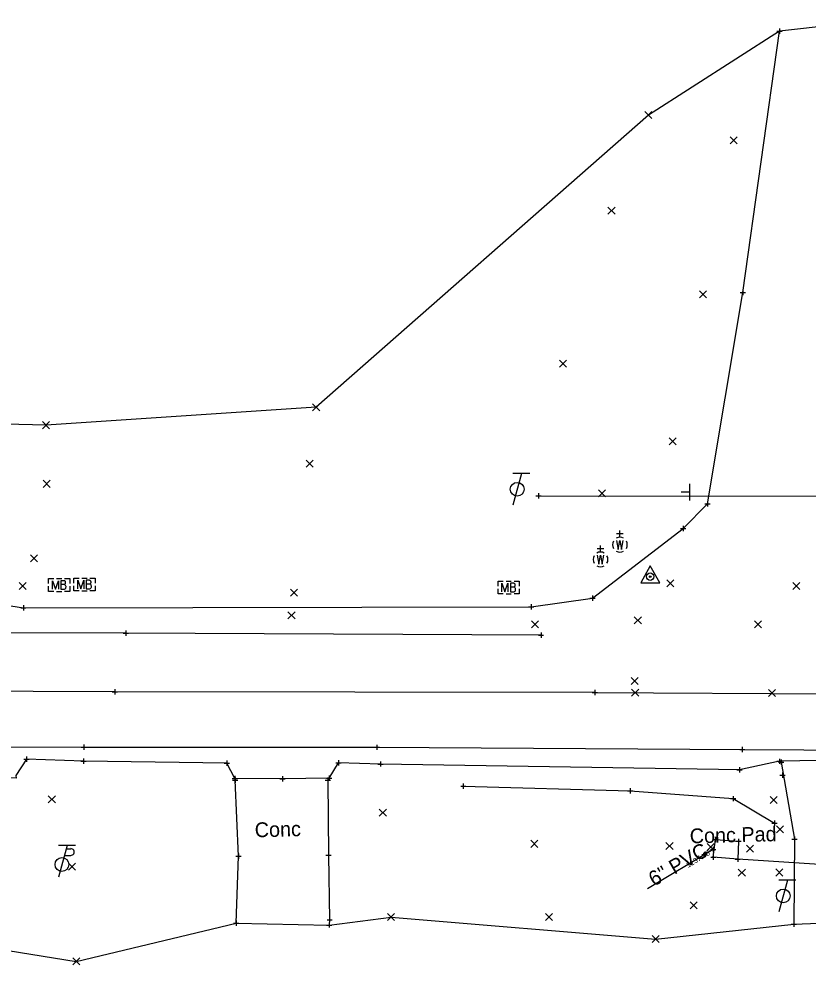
# Model space of a CAD drawing. Extents: x 146022 to 147632, y 437624 to 440659.
# Drawn here: x 146651.9 to 146801.3, y 438576.8 to 438756.1 of the extents above; entities that cross this region are included whole.
import ezdxf

# ---------------------------------------------------------------- set-up
doc = ezdxf.new("R2010")
doc.units = 0
for name, color, linetype in [('_CIVIL_CONSTRUCTION', 7, 'Continuous'), ('DR_P_Ditch', 7, 'Continuous'), ('DR_X_Storm_Sewer', 7, 'Continuous'), ('DR_X_Text', 7, 'Continuous'), ('DT_X_Break_Line', 7, 'Continuous'), ('DT_X_Contour_Major', 7, 'Continuous'), ('DT_X_Spot_Elev', 7, 'Continuous'), ('GE_P_Alignment_100_Distances', 7, 'Continuous'), ('PF_X_Ground_Line', 7, 'Continuous'), ('PV_P_Curb', 7, 'Continuous'), ('PV_P_Joint', 7, 'Continuous'), ('RD_P_Anchor_Assembly', 7, 'Continuous'), ('RD_P_GR_Lt_Replaced', 7, 'Continuous'), ('RD_P_GR_Rt', 7, 'Continuous'), ('SC_Scratch1', 7, 'Continuous'), ('SC_Scratch3', 7, 'Continuous'), ('SV_X_Terrain_Boundary', 7, 'Continuous'), ('UT_X_Overhead_Cable_TV', 7, 'Continuous'), ('UT_X_Overhead_Electric', 7, 'Continuous')]:
    doc.layers.add(name, color=color, linetype=linetype)

msp = doc.modelspace()

# ---------------------------------------------------------------- linework, layer by layer
at = {"layer": '_CIVIL_CONSTRUCTION'}
for p, q in [((146770.39, 438737.25), (146771.72, 438738.58)), ((146770.39, 438738.58), (146771.72, 438737.25)), ((146786.49, 438732.48), (146787.82, 438733.81)), ((146786.49, 438733.81), (146787.82, 438732.48)), ((146763.39, 438719.14), (146764.72, 438720.47)), ((146763.39, 438720.47), (146764.72, 438719.14)), ((146780.69, 438703.32), (146782.02, 438704.65)), ((146780.69, 438704.65), (146782.02, 438703.32)), ((146754.18, 438690.19), (146755.51, 438691.52)), ((146754.18, 438691.52), (146755.51, 438690.19)), ((146707.47, 438681.91), (146708.81, 438683.24)), ((146707.47, 438683.24), (146708.81, 438681.91)), ((146656.34, 438678.53), (146657.67, 438679.87)), ((146656.34, 438679.87), (146657.67, 438678.53)), ((146774.98, 438675.45), (146776.31, 438676.79)), ((146774.98, 438676.79), (146776.31, 438675.45)), ((146706.24, 438671.25), (146707.58, 438672.58)), ((146706.24, 438672.58), (146707.58, 438671.25)), ((146656.48, 438667.42), (146657.82, 438668.76)), ((146656.48, 438668.76), (146657.82, 438667.42)), ((146761.58, 438665.63), (146762.91, 438666.97)), ((146761.58, 438666.97), (146762.91, 438665.63)), ((146654.06, 438653.3), (146655.4, 438654.64)), ((146654.06, 438654.64), (146655.4, 438653.3)), ((146651.92, 438648.08), (146653.25, 438649.41)), ((146651.92, 438649.41), (146653.25, 438648.08)), ((146774.53, 438648.59), (146775.86, 438649.92)), ((146774.53, 438649.92), (146775.86, 438648.59)), ((146798.37, 438648.08), (146799.7, 438649.41)), ((146798.37, 438649.41), (146799.7, 438648.08)), ((146703.31, 438646.79), (146704.64, 438648.12)), ((146703.31, 438648.12), (146704.64, 438646.79)), ((146702.8, 438642.52), (146704.14, 438643.86)), ((146702.8, 438643.86), (146704.14, 438642.52)), ((146748.91, 438640.83), (146750.24, 438642.16)), ((146748.91, 438642.16), (146750.24, 438640.83)), ((146768.37, 438641.59), (146769.71, 438642.93)), ((146768.37, 438642.93), (146769.71, 438641.59)), ((146791.12, 438640.81), (146792.45, 438642.15)), ((146791.12, 438642.15), (146792.45, 438640.81)), ((146767.78, 438630.09), (146769.11, 438631.42)), ((146767.78, 438631.42), (146769.11, 438630.09)), ((146767.87, 438627.86), (146769.2, 438629.19)), ((146767.87, 438629.19), (146769.2, 438627.86)), ((146793.8, 438627.8), (146795.13, 438629.13)), ((146793.8, 438629.13), (146795.13, 438627.8)), ((146657.44, 438607.67), (146658.77, 438609)), ((146657.44, 438609), (146658.77, 438607.67)), ((146794.08, 438607.55), (146795.41, 438608.88)), ((146794.08, 438608.88), (146795.41, 438607.55)), ((146720.09, 438605.14), (146721.43, 438606.47)), ((146720.09, 438606.47), (146721.43, 438605.14)), ((146795.26, 438602.01), (146796.6, 438603.35)), ((146795.26, 438603.35), (146796.6, 438602.01)), ((146748.8, 438599.25), (146750.13, 438600.59)), ((146748.8, 438600.59), (146750.13, 438599.25)), ((146774.36, 438598.82), (146775.7, 438600.16)), ((146774.36, 438600.16), (146775.7, 438598.82)), ((146782.15, 438598.63), (146783.48, 438599.96)), ((146782.15, 438599.96), (146783.48, 438598.63)), ((146789.62, 438598.32), (146790.95, 438599.65)), ((146789.62, 438599.65), (146790.95, 438598.32)), ((146661.24, 438594.91), (146662.58, 438596.24)), ((146661.24, 438596.24), (146662.58, 438594.91)), ((146788.06, 438593.79), (146789.39, 438595.12)), ((146788.06, 438595.12), (146789.39, 438593.79)), ((146795.16, 438593.81), (146796.49, 438595.15)), ((146795.16, 438595.15), (146796.49, 438593.81)), ((146778.94, 438587.58), (146780.27, 438588.92)), ((146778.94, 438588.92), (146780.27, 438587.58)), ((146721.66, 438585.37), (146722.99, 438586.71)), ((146721.66, 438586.71), (146722.99, 438585.37)), ((146751.53, 438585.38), (146752.86, 438586.71)), ((146751.53, 438586.71), (146752.86, 438585.38)), ((146771.73, 438581.2), (146773.06, 438582.54)), ((146771.73, 438582.54), (146773.06, 438581.2)), ((146662.05, 438576.98), (146663.38, 438578.32)), ((146662.05, 438578.32), (146663.38, 438576.98))]:
    msp.add_line(p, q, dxfattribs=at)
at = {"layer": 'DR_P_Ditch'}
msp.add_lwpolyline([(146787.94, 438597.01), (146783.33, 438597.39), (146783.74, 438600.71), (146788.12, 438600.39)], close=True, dxfattribs=at)
at = {"layer": 'DR_X_Storm_Sewer'}
for p, q in [((146783.32, 438598.84), (146770.88, 438591.4)), ((146872.73, 438591.35), (146787.94, 438597.01))]:
    msp.add_line(p, q, dxfattribs=at)
at = {"layer": 'DT_X_Break_Line'}
for p, q in [((146778.85, 438668.11), (146778.85, 438664.91)), ((146778.85, 438666.51), (146777.25, 438666.51))]:
    msp.add_line(p, q, dxfattribs=at)
at = {"layer": 'DT_X_Contour_Major'}
for p, q in [((146660.99, 438599.6), (146659.38, 438593.6)), ((146662.59, 438599.6), (146659.39, 438599.6)), ((146660.83, 438599), (146661.68, 438599)), ((146660.49, 438597.73), (146661.68, 438597.73))]:
    msp.add_line(p, q, dxfattribs=at)
msp.add_circle((146660.02, 438596), 1.3, dxfattribs=at)
msp.add_arc((146661.69, 438598.37), 0.638, 268.8767, 91.1233, dxfattribs=at)
at = {"layer": 'DT_X_Spot_Elev'}
for p, q in [((146658.99, 438650.17), (146659.99, 438650.17)), ((146663.79, 438650.24), (146664.79, 438650.24)), ((146659.5, 438648.95), (146659.5, 438648.95)), ((146664.3, 438649.02), (146664.3, 438649.02)), ((146744.09, 438649.67), (146745.09, 438649.67)), ((146744.6, 438648.45), (146744.6, 438648.45)), ((146658.99, 438647.73), (146659.99, 438647.73)), ((146663.79, 438647.8), (146664.79, 438647.8)), ((146744.09, 438647.23), (146745.09, 438647.23))]:
    msp.add_line(p, q, dxfattribs=at)
for points in [[(146657.5, 438649.2), (146657.5, 438650.17), (146658.47, 438650.17)], [(146660.5, 438650.17), (146661.5, 438650.17), (146661.5, 438649.2)], [(146662.3, 438649.27), (146662.3, 438650.24), (146663.27, 438650.24)], [(146665.31, 438650.24), (146666.3, 438650.24), (146666.3, 438649.27)], [(146658.47, 438647.73), (146657.5, 438647.73), (146657.5, 438648.7)], [(146658.2, 438648.15), (146658.2, 438649.75), (146658.78, 438648.15), (146659.34, 438649.75), (146659.34, 438648.15)], [(146660.52, 438649.02), (146660.58, 438649.08), (146660.62, 438649.12), (146660.65, 438649.16), (146660.66, 438649.18), (146660.68, 438649.23), (146660.7, 438649.27), (146660.72, 438649.36), (146660.72, 438649.4), (146660.72, 438649.45), (146660.71, 438649.52), (146660.68, 438649.59), (146660.65, 438649.64), (146660.58, 438649.69), (146660.53, 438649.71), (146660.51, 438649.73), (146660.44, 438649.75), (146659.83, 438649.75), (146659.83, 438648.15), (146660.52, 438648.15), (146660.61, 438648.2), (146660.68, 438648.26), (146660.75, 438648.36), (146660.78, 438648.48), (146660.8, 438648.59), (146660.8, 438648.67), (146660.77, 438648.74), (146660.72, 438648.86), (146660.66, 438648.93), (146660.52, 438649.02), (146659.83, 438649.02)], [(146661.5, 438648.7), (146661.5, 438647.73), (146660.5, 438647.73)], [(146663.27, 438647.8), (146662.3, 438647.8), (146662.3, 438648.77)], [(146663, 438648.22), (146663, 438649.82), (146663.58, 438648.22), (146664.14, 438649.82), (146664.14, 438648.22)], [(146665.32, 438649.09), (146665.38, 438649.15), (146665.42, 438649.19), (146665.45, 438649.23), (146665.46, 438649.25), (146665.49, 438649.3), (146665.5, 438649.34), (146665.52, 438649.43), (146665.52, 438649.47), (146665.52, 438649.52), (146665.51, 438649.59), (146665.49, 438649.65), (146665.45, 438649.7), (146665.38, 438649.76), (146665.33, 438649.78), (146665.31, 438649.79), (146665.25, 438649.82), (146664.63, 438649.82), (146664.63, 438648.22), (146665.32, 438648.22), (146665.41, 438648.27), (146665.49, 438648.33), (146665.55, 438648.43), (146665.59, 438648.55), (146665.6, 438648.66), (146665.6, 438648.73), (146665.57, 438648.81), (146665.52, 438648.92), (146665.46, 438649), (146665.32, 438649.09), (146664.63, 438649.09)], [(146666.3, 438648.77), (146666.3, 438647.8), (146665.31, 438647.8)], [(146742.6, 438648.7), (146742.6, 438649.67), (146743.57, 438649.67)], [(146743.3, 438647.65), (146743.3, 438649.25), (146743.88, 438647.65), (146744.44, 438649.25), (146744.44, 438647.65)], [(146745.62, 438648.52), (146745.69, 438648.59), (146745.72, 438648.62), (146745.75, 438648.66), (146745.76, 438648.69), (146745.79, 438648.74), (146745.8, 438648.77), (146745.82, 438648.86), (146745.82, 438648.9), (146745.82, 438648.95), (146745.81, 438649.03), (146745.79, 438649.09), (146745.75, 438649.14), (146745.69, 438649.19), (146745.64, 438649.22), (146745.61, 438649.23), (146745.55, 438649.25), (146744.93, 438649.25), (146744.93, 438647.65), (146745.62, 438647.65), (146745.71, 438647.7), (146745.79, 438647.77), (146745.85, 438647.87), (146745.89, 438647.98), (146745.9, 438648.09), (146745.9, 438648.17), (146745.87, 438648.25), (146745.82, 438648.36), (146745.76, 438648.43), (146745.62, 438648.52), (146744.93, 438648.52)], [(146745.61, 438649.67), (146746.6, 438649.67), (146746.6, 438648.7)], [(146743.57, 438647.23), (146742.6, 438647.23), (146742.6, 438648.2)], [(146746.6, 438648.2), (146746.6, 438647.23), (146745.61, 438647.23)]]:
    msp.add_lwpolyline(points, dxfattribs=at)
at = {"layer": 'GE_P_Alignment_100_Distances'}
msp.add_lwpolyline([(146750.22, 438665.83), (146889.21, 438665.72), (146992.98, 438665.29), (147118.65, 438665.14)], dxfattribs=at)
at = {"layer": 'PF_X_Ground_Line'}
msp.add_lwpolyline([(146736, 438610.82), (146767.59, 438609.97), (146787.08, 438608.47), (146794.92, 438603.81)], dxfattribs=at)
at = {"layer": 'PV_P_Curb'}
msp.add_line((146760.89, 438628.57), (146831.42, 438628.2), dxfattribs=at)
msp.add_lwpolyline([(146760.89, 438628.57), (146670.03, 438628.72), (146608.22, 438628.98), (146536.84, 438628.93)], dxfattribs=at)
at = {"layer": 'PV_P_Joint'}
msp.add_lwpolyline([(146769.58, 438649.36), (146773.18, 438649.36), (146771.38, 438652.58)], close=True, dxfattribs=at)
for radius in [0.7, 0.16]:
    msp.add_circle((146771.38, 438650.51), radius, dxfattribs=at)
at = {"layer": 'RD_P_Anchor_Assembly'}
for p, q in [((146795.88, 438754.29), (146795.88, 438753.29)), ((146795.38, 438753.79), (146796.38, 438753.79)), ((146795.88, 438753.79), (146795.88, 438753.79)), ((146788.41, 438704.34), (146789.41, 438704.34)), ((146788.91, 438704.84), (146788.91, 438703.84)), ((146788.91, 438704.34), (146788.91, 438704.34)), ((146750.22, 438666.33), (146750.22, 438665.33)), ((146749.72, 438665.83), (146750.72, 438665.83)), ((146750.22, 438665.83), (146750.22, 438665.83)), ((146782.21, 438664.81), (146782.21, 438663.81)), ((146781.71, 438664.31), (146782.71, 438664.31)), ((146782.21, 438664.31), (146782.21, 438664.31)), ((146777.12, 438659.64), (146778.12, 438659.64)), ((146777.62, 438660.14), (146777.62, 438659.14)), ((146777.62, 438659.64), (146777.62, 438659.64)), ((146760.43, 438646.95), (146760.43, 438645.95)), ((146652.71, 438645.13), (146652.71, 438644.13)), ((146748.33, 438644.78), (146749.33, 438644.78)), ((146748.83, 438645.28), (146748.83, 438644.28)), ((146748.83, 438644.78), (146748.83, 438644.78)), ((146759.93, 438646.45), (146760.93, 438646.45)), ((146760.43, 438646.45), (146760.43, 438646.45)), ((146652.21, 438644.63), (146653.21, 438644.63)), ((146652.71, 438644.63), (146652.71, 438644.63)), ((146671.62, 438639.82), (146672.62, 438639.82)), ((146672.12, 438640.32), (146672.12, 438639.32)), ((146672.12, 438639.82), (146672.12, 438639.82)), ((146750.21, 438639.45), (146751.21, 438639.45)), ((146750.71, 438639.95), (146750.71, 438638.95)), ((146750.71, 438639.45), (146750.71, 438639.45)), ((146669.53, 438628.72), (146670.53, 438628.72)), ((146670.03, 438629.22), (146670.03, 438628.22)), ((146670.03, 438628.72), (146670.03, 438628.72)), ((146760.89, 438629.07), (146760.89, 438628.07)), ((146760.39, 438628.57), (146761.39, 438628.57)), ((146760.89, 438628.57), (146760.89, 438628.57)), ((146663.65, 438618.22), (146664.65, 438618.22)), ((146664.15, 438618.72), (146664.15, 438617.72)), ((146664.15, 438618.22), (146664.15, 438618.22)), ((146719.14, 438618.19), (146720.14, 438618.19)), ((146719.64, 438618.69), (146719.64, 438617.69)), ((146719.64, 438618.19), (146719.64, 438618.19)), ((146788.82, 438618.3), (146788.82, 438617.3)), ((146653.33, 438616.44), (146653.33, 438615.44)), ((146664.1, 438616.08), (146664.1, 438615.08)), ((146788.32, 438617.8), (146789.32, 438617.8)), ((146788.82, 438617.8), (146788.82, 438617.8)), ((146795.87, 438616.04), (146795.87, 438615.04)), ((146652.83, 438615.94), (146653.83, 438615.94)), ((146653.33, 438615.94), (146653.33, 438615.94)), ((146663.6, 438615.58), (146664.6, 438615.58)), ((146664.1, 438615.58), (146664.1, 438615.58)), ((146690.76, 438615.19), (146691.76, 438615.19)), ((146691.26, 438615.69), (146691.26, 438614.69)), ((146691.26, 438615.19), (146691.26, 438615.19)), ((146711.85, 438615.26), (146712.85, 438615.26)), ((146712.35, 438615.76), (146712.35, 438614.76)), ((146712.35, 438615.26), (146712.35, 438615.26)), ((146719.81, 438615.03), (146720.81, 438615.03)), ((146720.31, 438615.53), (146720.31, 438614.53)), ((146720.31, 438615.03), (146720.31, 438615.03)), ((146788.31, 438614.43), (146788.31, 438613.43)), ((146795.37, 438615.54), (146796.37, 438615.54)), ((146795.68, 438615.39), (146796.68, 438615.39)), ((146795.87, 438615.54), (146795.87, 438615.54)), ((146796.18, 438615.89), (146796.18, 438614.89)), ((146796.18, 438615.39), (146796.18, 438615.39)), ((146692.77, 438612.79), (146692.77, 438611.79)), ((146692.79, 438612.49), (146692.79, 438611.49)), ((146701.78, 438612.72), (146701.78, 438611.72)), ((146710.35, 438612.46), (146710.35, 438611.46)), ((146710.58, 438612.83), (146710.58, 438611.83)), ((146787.81, 438613.93), (146788.81, 438613.93)), ((146788.31, 438613.93), (146788.31, 438613.93)), ((146795.93, 438612.92), (146796.93, 438612.92)), ((146796.43, 438613.42), (146796.43, 438612.42)), ((146796.43, 438612.92), (146796.43, 438612.92)), ((146692.27, 438612.29), (146693.27, 438612.29)), ((146692.29, 438611.99), (146693.29, 438611.99)), ((146692.77, 438612.29), (146692.77, 438612.29)), ((146692.79, 438611.99), (146692.79, 438611.99)), ((146701.28, 438612.22), (146702.28, 438612.22)), ((146701.78, 438612.22), (146701.78, 438612.22)), ((146709.85, 438611.96), (146710.85, 438611.96)), ((146710.08, 438612.33), (146711.08, 438612.33)), ((146710.35, 438611.96), (146710.35, 438611.96)), ((146710.58, 438612.33), (146710.58, 438612.33)), ((146735.5, 438610.82), (146736.5, 438610.82)), ((146736, 438611.32), (146736, 438610.32)), ((146736, 438610.82), (146736, 438610.82)), ((146767.09, 438609.97), (146768.09, 438609.97)), ((146767.59, 438610.47), (146767.59, 438609.47)), ((146767.59, 438609.97), (146767.59, 438609.97)), ((146787.08, 438608.97), (146787.08, 438607.97)), ((146786.58, 438608.47), (146787.58, 438608.47)), ((146787.08, 438608.47), (146787.08, 438608.47)), ((146794.42, 438603.81), (146795.42, 438603.81)), ((146794.92, 438604.31), (146794.92, 438603.31)), ((146794.92, 438603.81), (146794.92, 438603.81)), ((146783.24, 438600.71), (146784.24, 438600.71)), ((146783.74, 438601.21), (146783.74, 438600.21)), ((146783.74, 438600.71), (146783.74, 438600.71)), ((146787.62, 438600.39), (146788.62, 438600.39)), ((146788.12, 438600.89), (146788.12, 438599.89)), ((146788.12, 438600.39), (146788.12, 438600.39)), ((146798.19, 438600.83), (146799.19, 438600.83)), ((146798.69, 438601.33), (146798.69, 438600.33)), ((146798.69, 438600.83), (146798.69, 438600.83)), ((146710.5, 438598.3), (146710.5, 438597.3)), ((146692.93, 438597.59), (146693.93, 438597.59)), ((146693.43, 438598.09), (146693.43, 438597.09)), ((146693.43, 438597.59), (146693.43, 438597.59)), ((146710, 438597.8), (146711, 438597.8)), ((146710.5, 438597.8), (146710.5, 438597.8)), ((146782.83, 438597.39), (146783.83, 438597.39)), ((146783.33, 438597.89), (146783.33, 438596.89)), ((146783.33, 438597.39), (146783.33, 438597.39)), ((146787.44, 438597.01), (146788.44, 438597.01)), ((146787.94, 438597.51), (146787.94, 438596.51)), ((146787.94, 438597.01), (146787.94, 438597.01)), ((146710.2, 438585.55), (146711.2, 438585.55)), ((146710.7, 438586.05), (146710.7, 438585.05)), ((146710.7, 438585.55), (146710.7, 438585.55)), ((146692.49, 438584.88), (146693.49, 438584.88)), ((146692.99, 438585.38), (146692.99, 438584.38)), ((146692.99, 438584.88), (146692.99, 438584.88)), ((146710.12, 438584.54), (146711.12, 438584.54)), ((146710.62, 438585.04), (146710.62, 438584.04)), ((146710.62, 438584.54), (146710.62, 438584.54)), ((146798.07, 438584.69), (146799.07, 438584.69)), ((146798.57, 438585.19), (146798.57, 438584.19)), ((146798.57, 438584.69), (146798.57, 438584.69))]:
    msp.add_line(p, q, dxfattribs=at)
at = {"layer": 'RD_P_GR_Lt_Replaced'}
msp.add_line((146710.58, 438612.33), (146712.35, 438615.26), dxfattribs=at)
for points in [[(146550.45, 438642.82), (146591.71, 438643.54), (146623.43, 438643.48), (146625.75, 438645.31), (146647.52, 438645.41), (146652.71, 438644.63), (146748.83, 438644.78), (146760.43, 438646.45), (146777.62, 438659.64), (146782.21, 438664.31), (146788.91, 438704.34), (146795.88, 438753.79)], [(146710.58, 438612.33), (146701.78, 438612.22), (146692.77, 438612.29), (146691.26, 438615.19), (146664.1, 438615.58), (146653.33, 438615.94), (146651.3, 438612.85), (146651.34, 438612.38), (146636.52, 438612.47), (146636.36, 438612.78), (146633.57, 438615.43), (146597.09, 438615.99), (146543.16, 438616.38)], [(146880.85, 438613.68), (146860.56, 438614.41), (146837.82, 438613.79), (146818.89, 438614.33), (146818.92, 438615.92), (146795.87, 438615.54), (146788.31, 438613.93), (146720.31, 438615.03), (146712.35, 438615.26)]]:
    msp.add_lwpolyline(points, dxfattribs=at)
at = {"layer": 'RD_P_GR_Rt'}
for p, q in [((146765.65, 438657.96), (146765.65, 438659.23)), ((146766.29, 438658.6), (146765.02, 438658.6)), ((146762.61, 438655.81), (146761.34, 438655.81)), ((146761.98, 438655.17), (146761.98, 438656.44)), ((146765.65, 438656.56), (146765.65, 438656.56)), ((146761.98, 438653.77), (146761.98, 438653.77))]:
    msp.add_line(p, q, dxfattribs=at)
for points in [[(146765.02, 438657.38), (146765.34, 438655.66), (146765.65, 438657.38), (146765.97, 438655.66), (146766.29, 438657.38)], [(146761.34, 438654.59), (146761.66, 438652.87), (146761.98, 438654.59), (146762.3, 438652.87), (146762.61, 438654.59)]]:
    msp.add_lwpolyline(points, dxfattribs=at)
for centre, start, end in [((146765.65, 438656.56), 60.0184, 120.0157), ((146765.65, 438656.56), 150.0184, 209.9816), ((146765.65, 438656.56), 330.0184, 29.9816), ((146761.98, 438653.77), 150.0184, 209.9816), ((146761.98, 438653.77), 60.0184, 120.0157), ((146761.98, 438653.77), 330.0184, 29.9816), ((146765.65, 438656.56), 239.9843, 299.9816), ((146761.98, 438653.77), 239.9843, 299.9816)]:
    msp.add_arc(centre, 1.4, start, end, dxfattribs=at)
at = {"layer": 'SC_Scratch1'}
for points in [[(146796.18, 438615.39), (146798.69, 438600.83), (146798.57, 438584.69)], [(146692.99, 438584.88), (146693.43, 438597.59), (146692.79, 438611.99)], [(146710.35, 438611.96), (146710.5, 438597.8), (146710.7, 438585.55), (146710.62, 438584.54)]]:
    msp.add_lwpolyline(points, dxfattribs=at)
at = {"layer": 'SC_Scratch3'}
for points in [[(146750.71, 438639.45), (146672.12, 438639.82), (146607.96, 438639.96), (146541.22, 438639.78)], [(146543.08, 438618.44), (146597.03, 438618.35), (146664.15, 438618.22), (146719.64, 438618.19), (146788.82, 438617.8), (146882.32, 438617.3)]]:
    msp.add_lwpolyline(points, dxfattribs=at)
at = {"layer": 'SV_X_Terrain_Boundary'}
msp.add_lwpolyline([(146816.74, 438756.13), (146795.88, 438753.79), (146771.05, 438737.91), (146708.14, 438682.58), (146657.01, 438679.2), (146644.05, 438679.52), (146633.65, 438679.48), (146551.11, 438671.21), (146544.22, 438654.47), (146542.4, 438642.93), (146541.22, 438639.78), (146536.84, 438628.93), (146543.08, 438618.44), (146543.16, 438616.38), (146540.39, 438582.97), (146637.92, 438576.77), (146649.84, 438579.7), (146662.72, 438577.65), (146692.99, 438584.88), (146710.62, 438584.54), (146722.32, 438586.04), (146772.4, 438581.87), (146798.57, 438584.69), (146815.95, 438585.38)], dxfattribs=at)
at = {"layer": 'UT_X_Overhead_Cable_TV'}
for p, q in [((146748.6, 438670.06), (146745.4, 438670.06)), ((146747, 438670.06), (146745.4, 438664.06)), ((146797.36, 438593.04), (146795.75, 438587.04)), ((146798.96, 438593.04), (146795.76, 438593.04))]:
    msp.add_line(p, q, dxfattribs=at)
for centre in [(146746.2, 438667.06), (146796.56, 438590.04)]:
    msp.add_circle(centre, 1.3, dxfattribs=at)
at = {"layer": 'UT_X_Overhead_Electric'}
for p, q in [((146781.67, 438598.42), (146781.67, 438597.42)), ((146782.82, 438598.84), (146783.82, 438598.84)), ((146783.32, 438599.34), (146783.32, 438598.34)), ((146783.32, 438598.84), (146783.32, 438598.84)), ((146781.17, 438597.92), (146782.17, 438597.92)), ((146781.67, 438597.92), (146781.67, 438597.92))]:
    msp.add_line(p, q, dxfattribs=at)

# ---------------------------------------------------------------- texts
at = {"layer": 'DR_X_Text'}
for s, rotation, p in [('Conc', 1.4771, (146696.55, 438601.15)), ('Conc Pad', 1.4771, (146778.9, 438600)), ('6" PVC', 30, (146772.1, 438591.79))]:
    msp.add_text(s, height=2.8, rotation=rotation, dxfattribs=at).set_placement(p)
at = {"layer": 'SC_Scratch1'}
msp.add_text("1137.48'", height=1, rotation=30.8901, dxfattribs=at).set_placement((146778.54, 438595.34))

doc.saveas('drawing.dxf')
